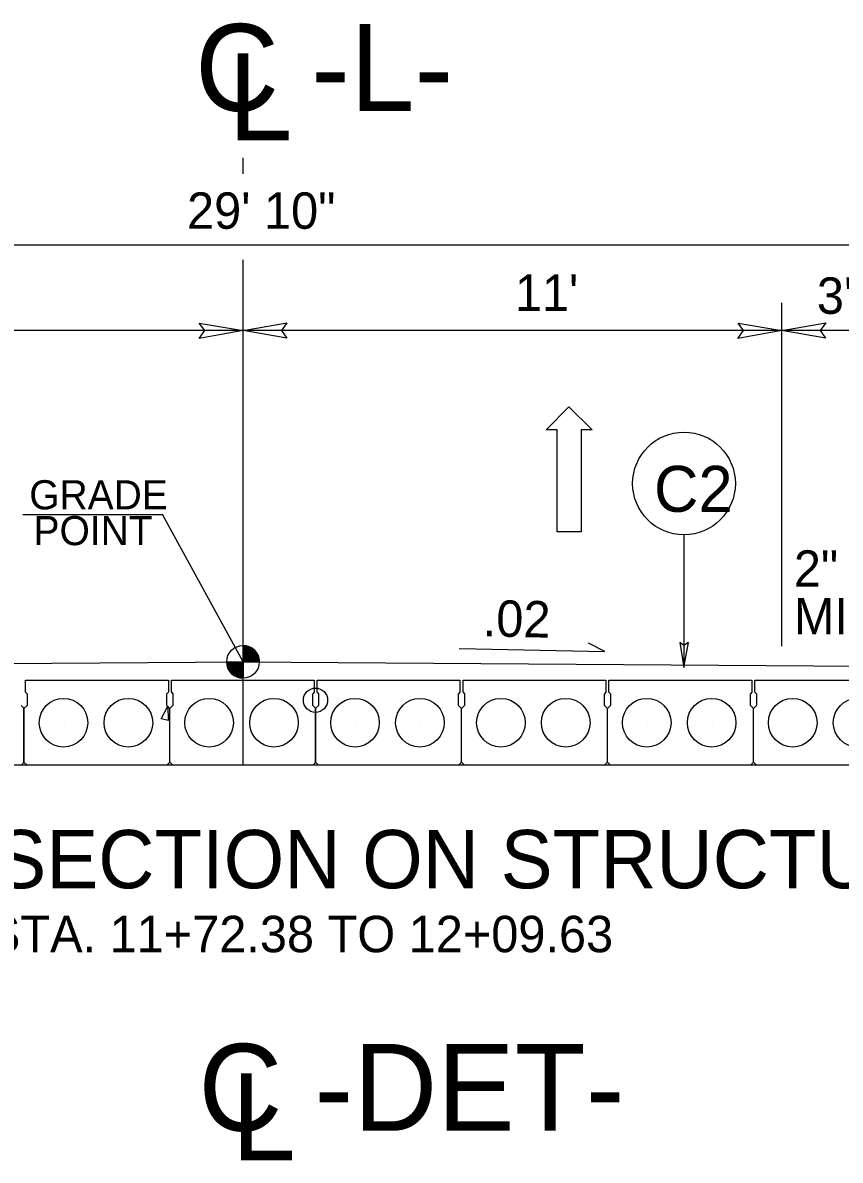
# Model space of a CAD drawing. Extents: x 575722 to 576066, y -53107 to -52774.
# Drawn here: x 575833.77 to 575850.61, y -53081.36 to -53057.93 of the extents above; entities that cross this region are included whole.
import ezdxf

# ---------------------------------------------------------------- set-up
doc = ezdxf.new("R2010")
doc.units = 0
for name, color, linetype in [('Default', 7, 'Continuous'), ('Old_Level_1', 7, 'Continuous'), ('Old_Level_11', 7, 'Continuous'), ('Old_Level_2', 7, 'Continuous'), ('Old_Level_3', 7, 'Continuous'), ('Prop Dimension Text', 7, 'Continuous'), ('Prop DSN Text', 7, 'Continuous'), ('Prop Lane Arrow CELL', 7, 'Continuous'), ('Typical Grade Point Symbol CELL', 7, 'Continuous'), ('Typical ID Circle CELL', 7, 'Continuous'), ('Typical Pavement Slope CELL', 7, 'Continuous'), ('Typical Terminator CELL', 7, 'Continuous'), ('Typical Text ID Circle CELL', 7, 'Continuous')]:
    doc.layers.add(name, color=color, linetype=linetype)

msp = doc.modelspace()

# ---------------------------------------------------------------- linework, layer by layer
at = {"layer": 'Default'}
for p, q in [((575833.797, -53071.47), (575833.797, -53071.47)), ((575833.827, -53071.721), (575833.827, -53071.47)), ((575833.827, -53071.47), (575836.771, -53071.47)), ((575836.771, -53071.47), (575836.771, -53071.721)), ((575836.802, -53071.47), (575836.802, -53071.47)), ((575836.832, -53071.721), (575836.832, -53071.47)), ((575836.832, -53071.47), (575839.776, -53071.47)), ((575839.776, -53071.47), (575839.776, -53071.721)), ((575839.802, -53071.47), (575839.802, -53071.47)), ((575839.807, -53071.47), (575839.807, -53071.47)), ((575839.832, -53071.721), (575839.832, -53071.47)), ((575839.832, -53071.47), (575842.776, -53071.47)), ((575842.776, -53071.47), (575842.776, -53071.721)), ((575842.807, -53071.47), (575842.807, -53071.47)), ((575842.809, -53071.47), (575842.809, -53071.47)), ((575842.839, -53071.721), (575842.839, -53071.47)), ((575842.839, -53071.47), (575845.783, -53071.47)), ((575845.783, -53071.47), (575845.783, -53071.721)), ((575845.814, -53071.47), (575845.814, -53071.47)), ((575845.815, -53071.47), (575845.815, -53071.47)), ((575845.845, -53071.721), (575845.845, -53071.47)), ((575845.845, -53071.47), (575848.789, -53071.47)), ((575848.789, -53071.47), (575848.789, -53071.721)), ((575848.821, -53071.47), (575848.821, -53071.47)), ((575848.822, -53071.47), (575848.822, -53071.47)), ((575848.852, -53071.721), (575848.852, -53071.47)), ((575848.852, -53071.47), (575851.796, -53071.47)), ((575833.827, -53071.721), (575833.858, -53071.752)), ((575836.771, -53071.721), (575836.739, -53071.752)), ((575836.832, -53071.721), (575836.863, -53071.752)), ((575839.776, -53071.721), (575839.745, -53071.752)), ((575839.832, -53071.721), (575839.863, -53071.752)), ((575842.776, -53071.721), (575842.744, -53071.752)), ((575842.839, -53071.721), (575842.87, -53071.752)), ((575845.783, -53071.721), (575845.751, -53071.752)), ((575845.845, -53071.721), (575845.877, -53071.752)), ((575848.789, -53071.721), (575848.758, -53071.752)), ((575848.852, -53071.721), (575848.883, -53071.752)), ((575833.858, -53071.752), (575833.858, -53071.992)), ((575836.739, -53071.992), (575836.739, -53071.752)), ((575836.863, -53071.752), (575836.863, -53071.992)), ((575839.745, -53071.992), (575839.745, -53071.752)), ((575839.863, -53071.752), (575839.863, -53071.992)), ((575842.744, -53071.992), (575842.744, -53071.752)), ((575842.87, -53071.752), (575842.87, -53071.992)), ((575845.751, -53071.992), (575845.751, -53071.752)), ((575845.877, -53071.752), (575845.877, -53071.992)), ((575848.758, -53071.992), (575848.758, -53071.752)), ((575848.883, -53071.752), (575848.883, -53071.992)), ((575833.797, -53072.055), (575833.734, -53071.992)), ((575833.795, -53072.055), (575833.858, -53071.992)), ((575833.795, -53073.161), (575833.795, -53072.055)), ((575833.797, -53073.161), (575833.797, -53072.055)), ((575836.802, -53072.055), (575836.739, -53071.992)), ((575836.801, -53072.055), (575836.863, -53071.992)), ((575836.801, -53073.161), (575836.801, -53072.055)), ((575836.802, -53073.161), (575836.802, -53072.055)), ((575839.807, -53072.055), (575839.745, -53071.992)), ((575839.801, -53072.055), (575839.863, -53071.992)), ((575839.802, -53073.161), (575839.802, -53072.055)), ((575839.806, -53073.161), (575839.806, -53072.055)), ((575842.807, -53072.055), (575842.744, -53071.992)), ((575842.807, -53072.055), (575842.87, -53071.992)), ((575842.807, -53073.161), (575842.807, -53072.055)), ((575842.809, -53073.161), (575842.809, -53072.055)), ((575845.814, -53072.055), (575845.751, -53071.992)), ((575845.814, -53072.055), (575845.877, -53071.992)), ((575845.814, -53073.161), (575845.814, -53072.055)), ((575845.815, -53073.161), (575845.815, -53072.055)), ((575848.821, -53072.055), (575848.758, -53071.992)), ((575848.821, -53072.055), (575848.883, -53071.992)), ((575848.821, -53073.161), (575848.821, -53072.055)), ((575848.822, -53073.161), (575848.822, -53072.055)), ((575834.631, -53072.347), (575834.631, -53072.347)), ((575835.967, -53072.347), (575835.967, -53072.347)), ((575837.609, -53072.347), (575837.609, -53072.347)), ((575838.945, -53072.347), (575838.945, -53072.347)), ((575840.636, -53072.347), (575840.636, -53072.347)), ((575841.972, -53072.347), (575841.972, -53072.347)), ((575843.642, -53072.347), (575843.642, -53072.347)), ((575844.979, -53072.347), (575844.979, -53072.347)), ((575846.649, -53072.347), (575846.649, -53072.347)), ((575847.985, -53072.347), (575847.985, -53072.347)), ((575849.656, -53072.347), (575849.656, -53072.347)), ((575854.778, -53073.224), (575821.837, -53073.224)), ((575833.797, -53073.161), (575833.734, -53073.224)), ((575833.858, -53073.224), (575833.795, -53073.161)), ((575836.739, -53073.224), (575833.858, -53073.224)), ((575836.739, -53073.224), (575833.858, -53073.224)), ((575836.802, -53073.161), (575836.739, -53073.224)), ((575836.863, -53073.224), (575836.801, -53073.161)), ((575839.745, -53073.224), (575836.863, -53073.224)), ((575839.745, -53073.224), (575836.863, -53073.224)), ((575839.807, -53073.161), (575839.745, -53073.224)), ((575839.863, -53073.224), (575839.801, -53073.161)), ((575842.744, -53073.224), (575839.863, -53073.224)), ((575842.807, -53073.161), (575842.744, -53073.224)), ((575842.87, -53073.224), (575842.807, -53073.161)), ((575845.751, -53073.224), (575842.87, -53073.224)), ((575845.814, -53073.161), (575845.751, -53073.224)), ((575845.877, -53073.224), (575845.814, -53073.161)), ((575848.758, -53073.224), (575845.877, -53073.224)), ((575848.821, -53073.161), (575848.758, -53073.224)), ((575848.883, -53073.224), (575848.821, -53073.161)), ((575851.764, -53073.224), (575848.883, -53073.224))]:
    msp.add_line(p, q, dxfattribs=at)
msp.add_lwpolyline([(575823.534, -53071.199), (575838.307, -53071.093), (575853.007, -53071.199)], dxfattribs=at)
msp.add_lwpolyline([(575836.755, -53072.007), (575836.762, -53072.302), (575836.623, -53072.27)], close=True, dxfattribs=at)
for centre, radius in [((575839.8, -53071.883), 0.25), ((575834.609, -53072.347), 0.501), ((575835.945, -53072.347), 0.501), ((575837.609, -53072.347), 0.501), ((575838.945, -53072.347), 0.501), ((575840.614, -53072.347), 0.501), ((575841.95, -53072.347), 0.501), ((575843.619, -53072.347), 0.501), ((575844.955, -53072.347), 0.501), ((575846.624, -53072.347), 0.501), ((575847.961, -53072.347), 0.501), ((575849.63, -53072.347), 0.501), ((575850.966, -53072.347), 0.501)]:
    msp.add_circle(centre, radius, dxfattribs=at)
at = {"layer": 'Old_Level_1'}
msp.add_line((575838.307, -53073.224), (575838.307, -53071.093), dxfattribs=at)
at = {"layer": 'Old_Level_11'}
for p, q in [((575853.007, -53062.514), (575823.534, -53062.515)), ((575849.407, -53070.769), (575849.407, -53063.698)), ((575843.334, -53064.271), (575827.134, -53064.271)), ((575849.407, -53064.271), (575833.207, -53064.271)), ((575853.007, -53064.271), (575849.407, -53064.271)), ((575833.773, -53068.06), (575836.65, -53068.06)), ((575838.307, -53071.093), (575836.65, -53068.06))]:
    msp.add_line(p, q, dxfattribs=at)
for points in [[(575837.407, -53064.116), (575838.307, -53064.271), (575837.402, -53064.431), (575837.517, -53064.271)], [(575839.207, -53064.426), (575838.307, -53064.271), (575839.212, -53064.111), (575839.097, -53064.271)], [(575848.507, -53064.116), (575849.407, -53064.271), (575848.502, -53064.431), (575848.617, -53064.271)], [(575850.307, -53064.426), (575849.407, -53064.271), (575850.312, -53064.112), (575850.197, -53064.271)]]:
    msp.add_lwpolyline(points, close=True, dxfattribs=at)
at = {"layer": 'Old_Level_2'}
for p, q in [((575838.307, -53061.043), (575838.307, -53060.712)), ((575838.307, -53072.783), (575838.307, -53062.816)), ((575838.307, -53067.71), (575838.307, -53067.504))]:
    msp.add_line(p, q, dxfattribs=at)
at = {"layer": 'Prop Lane Arrow CELL'}
for p, q in [((575844.551, -53066.314), (575845.016, -53065.841)), ((575845.016, -53065.841), (575845.496, -53066.314)), ((575844.776, -53066.314), (575844.551, -53066.314)), ((575844.776, -53068.414), (575844.776, -53066.314)), ((575845.496, -53066.314), (575845.271, -53066.314)), ((575845.271, -53066.314), (575845.271, -53068.414)), ((575845.271, -53068.414), (575844.776, -53068.414))]:
    msp.add_line(p, q, dxfattribs=at)
at = {"layer": 'Typical Grade Point Symbol CELL'}
for p, q in [((575838.307, -53071.093), (575838.307, -53070.757)), ((575837.972, -53071.093), (575838.307, -53071.093)), ((575838.643, -53071.093), (575838.307, -53071.093)), ((575838.307, -53071.429), (575838.307, -53071.093)), ((575838.307, -53071.093), (575838.307, -53071.429))]:
    msp.add_line(p, q, dxfattribs=at)
for points in [[(575838.31, -53070.757), (575838.31, -53070.757), (575838.31, -53071.093)], [(575838.317, -53070.757), (575838.317, -53071.093)], [(575838.324, -53070.758), (575838.324, -53071.093)], [(575838.33, -53070.758), (575838.33, -53071.093)], [(575838.337, -53070.759), (575838.337, -53071.093)], [(575838.344, -53070.76), (575838.344, -53071.093)], [(575838.351, -53070.76), (575838.351, -53071.093)], [(575838.357, -53070.761), (575838.357, -53071.093)], [(575838.364, -53070.762), (575838.364, -53071.093)], [(575838.371, -53070.763), (575838.371, -53071.093)], [(575838.377, -53070.765), (575838.377, -53071.093)], [(575838.384, -53070.766), (575838.384, -53071.093)], [(575838.391, -53070.768), (575838.391, -53071.093)], [(575838.398, -53070.77), (575838.398, -53071.093)], [(575838.404, -53070.772), (575838.404, -53071.093)], [(575838.411, -53070.774), (575838.411, -53071.093)], [(575838.418, -53070.776), (575838.418, -53071.093)], [(575838.424, -53070.778), (575838.424, -53071.093)], [(575838.431, -53070.781), (575838.431, -53071.093)], [(575838.438, -53070.784), (575838.438, -53071.093)], [(575838.445, -53070.787), (575838.445, -53071.093)], [(575838.451, -53070.79), (575838.451, -53071.093)], [(575838.458, -53070.793), (575838.458, -53071.093)], [(575838.465, -53070.797), (575838.465, -53071.093)], [(575838.471, -53070.801), (575838.471, -53071.093)], [(575838.478, -53070.804), (575838.478, -53071.093)], [(575838.485, -53070.808), (575838.485, -53071.093)], [(575838.492, -53070.813), (575838.492, -53071.093)], [(575838.498, -53070.817), (575838.498, -53071.093)], [(575838.505, -53070.822), (575838.505, -53071.093)], [(575838.512, -53070.827), (575838.512, -53071.093)], [(575838.518, -53070.832), (575838.518, -53071.093)], [(575838.525, -53070.838), (575838.525, -53071.093)], [(575838.532, -53070.844), (575838.532, -53071.093)], [(575838.539, -53070.85), (575838.539, -53071.093)], [(575838.545, -53070.857), (575838.545, -53071.093)], [(575838.552, -53070.863), (575838.552, -53071.093)], [(575838.559, -53070.871), (575838.559, -53071.093)], [(575838.565, -53070.879), (575838.565, -53071.093)], [(575838.572, -53070.887), (575838.572, -53071.093)], [(575838.579, -53070.896), (575838.579, -53071.093)], [(575838.586, -53070.906), (575838.586, -53071.093)], [(575838.592, -53070.916), (575838.592, -53071.093)], [(575838.599, -53070.928), (575838.599, -53071.093)], [(575838.606, -53070.939), (575838.606, -53071.093)], [(575838.612, -53070.954), (575838.612, -53071.093)], [(575838.619, -53070.969), (575838.619, -53071.093)], [(575838.626, -53070.988), (575838.626, -53071.093)], [(575838.633, -53071.011), (575838.633, -53071.093)], [(575837.973, -53071.093), (575837.973, -53071.13)], [(575837.98, -53071.093), (575837.98, -53071.169)], [(575837.987, -53071.093), (575837.987, -53071.193)], [(575837.993, -53071.093), (575837.993, -53071.213)], [(575838, -53071.093), (575838, -53071.229)], [(575838.007, -53071.093), (575838.007, -53071.243)], [(575838.013, -53071.093), (575838.013, -53071.256)], [(575838.02, -53071.093), (575838.02, -53071.268)], [(575838.027, -53071.093), (575838.027, -53071.278)], [(575838.034, -53071.093), (575838.034, -53071.288)], [(575838.04, -53071.093), (575838.04, -53071.297)], [(575838.047, -53071.093), (575838.047, -53071.305)], [(575838.054, -53071.093), (575838.054, -53071.313)], [(575838.06, -53071.093), (575838.06, -53071.321)], [(575838.067, -53071.093), (575838.067, -53071.328)], [(575838.074, -53071.093), (575838.074, -53071.335)], [(575838.081, -53071.093), (575838.081, -53071.341)], [(575838.087, -53071.093), (575838.087, -53071.347)], [(575838.094, -53071.093), (575838.094, -53071.353)], [(575838.101, -53071.093), (575838.101, -53071.358)], [(575838.107, -53071.093), (575838.107, -53071.363)], [(575838.114, -53071.093), (575838.114, -53071.368)], [(575838.121, -53071.093), (575838.121, -53071.372)], [(575838.128, -53071.093), (575838.128, -53071.377)], [(575838.134, -53071.093), (575838.134, -53071.381)], [(575838.141, -53071.093), (575838.141, -53071.385)], [(575838.148, -53071.093), (575838.148, -53071.389)], [(575838.154, -53071.093), (575838.154, -53071.392)], [(575838.161, -53071.093), (575838.161, -53071.395)], [(575838.168, -53071.093), (575838.168, -53071.398)], [(575838.175, -53071.093), (575838.175, -53071.401)], [(575838.181, -53071.093), (575838.181, -53071.404)], [(575838.188, -53071.093), (575838.188, -53071.407)], [(575838.195, -53071.093), (575838.195, -53071.409)], [(575838.201, -53071.093), (575838.201, -53071.412)], [(575838.208, -53071.093), (575838.208, -53071.414)], [(575838.215, -53071.093), (575838.215, -53071.415)], [(575838.222, -53071.093), (575838.222, -53071.418)], [(575838.228, -53071.093), (575838.228, -53071.419)], [(575838.235, -53071.093), (575838.235, -53071.421)], [(575838.242, -53071.093), (575838.242, -53071.422)], [(575838.248, -53071.093), (575838.248, -53071.424)], [(575838.255, -53071.093), (575838.255, -53071.424)], [(575838.262, -53071.093), (575838.262, -53071.426)], [(575838.269, -53071.093), (575838.269, -53071.427)], [(575838.275, -53071.093), (575838.275, -53071.427)], [(575838.282, -53071.093), (575838.282, -53071.428)], [(575838.289, -53071.093), (575838.289, -53071.428)], [(575838.295, -53071.093), (575838.295, -53071.429)], [(575838.302, -53071.093), (575838.302, -53071.429), (575838.302, -53071.429)], [(575838.639, -53071.045), (575838.639, -53071.093)]]:
    msp.add_lwpolyline(points, dxfattribs=at)
msp.add_circle((575838.307, -53071.093), 0.336, dxfattribs=at)
for start, end in [(359.9905, 89.9905), (179.9905, 269.9905)]:
    msp.add_arc((575838.307, -53071.093), 0.336, start, end, dxfattribs=at)
at = {"layer": 'Typical ID Circle CELL'}
msp.add_line((575847.391, -53068.477), (575847.391, -53071.211), dxfattribs=at)
msp.add_circle((575847.391, -53067.42), 1.058, dxfattribs=at)
at = {"layer": 'Typical Pavement Slope CELL'}
for p, q in [((575845.757, -53070.878), (575845.424, -53070.711)), ((575842.757, -53070.815), (575845.757, -53070.878))]:
    msp.add_line(p, q, dxfattribs=at)
at = {"layer": 'Typical Terminator CELL'}
msp.add_lwpolyline([(575847.303, -53070.696), (575847.391, -53071.211), (575847.483, -53070.693), (575847.391, -53070.759)], close=True, dxfattribs=at)

# ---------------------------------------------------------------- texts
at = {"layer": 'Old_Level_1'}
msp.add_text('.02', height=0.75, rotation=358.8084, dxfattribs=at).set_placement((575843.239, -53070.567))
at = {"layer": 'Old_Level_11'}
for s, p in [('29\' 10"', (575837.154, -53062.175)), ("11'", (575843.906, -53063.866)), ('3\' 11"', (575850.129, -53063.926)), ('2"', (575849.654, -53069.547)), ('MIN.', (575849.654, -53070.53))]:
    msp.add_text(s, height=0.75, rotation=360, dxfattribs=at).set_placement(p)
at = {"layer": 'Old_Level_3'}
for s, p in [('GRADE', (575833.904, -53067.953)), ('POINT', (575833.992, -53068.69))]:
    msp.add_text(s, height=0.6, rotation=360, dxfattribs=at).set_placement(p)
at = {"layer": 'Prop Dimension Text'}
msp.add_text('TYPICAL SECTION ON STRUCTURE', height=1.2, dxfattribs=at).set_placement((575826.049, -53075.756))
at = {"layer": 'Prop DSN Text'}
for s, height, p in [('C -L-', 1.7897, (575837.32, -53059.748)), ('L', 1.79, (575837.997, -53060.354)), ('-L- STA. 11+72.38 TO 12+09.63', 0.75, (575831.547, -53077.073)), ('C -DET-', 1.7897, (575837.389, -53080.751)), ('L', 1.79, (575838.066, -53081.357))]:
    msp.add_text(s, height=height, dxfattribs=at).set_placement(p)
at = {"layer": 'Typical Text ID Circle CELL'}
msp.add_text('C2', height=0.9469, dxfattribs=at).set_placement((575846.774, -53068.004))

doc.saveas('drawing.dxf')
